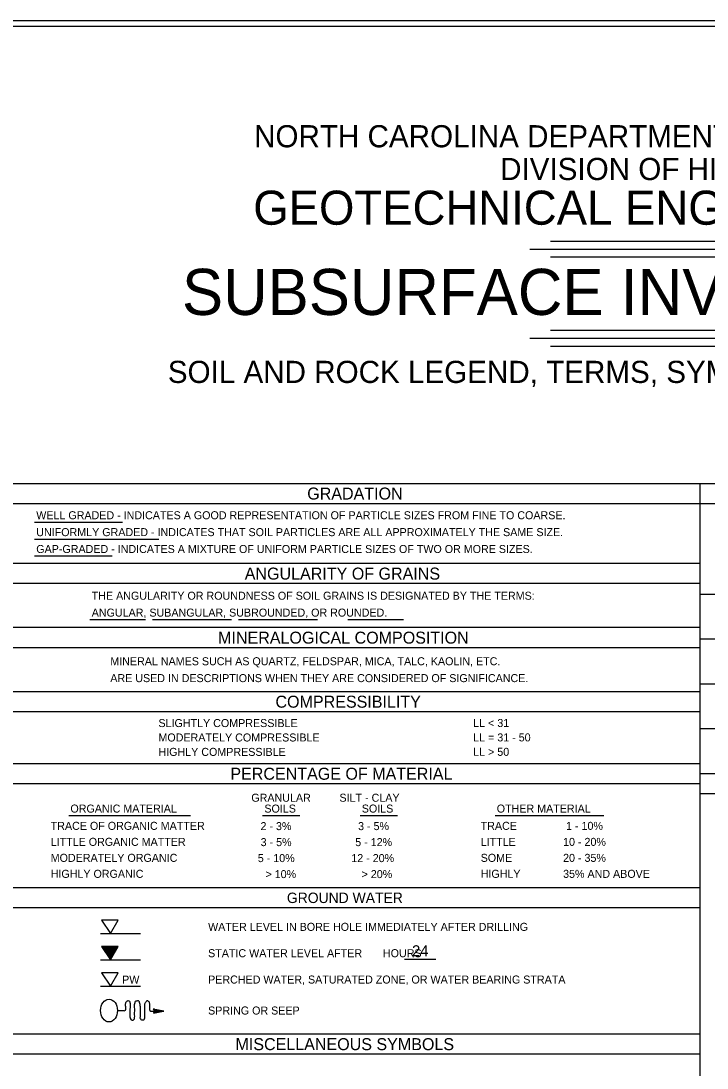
# Model space of a CAD drawing. Extents: x 265553 to 275568, y 168312 to 173522.
# Drawn here: x 267302 to 267674, y 170735 to 171303 of the extents above; entities that cross this region are included whole.
import ezdxf

# ---------------------------------------------------------------- set-up
doc = ezdxf.new("R2010")
doc.units = 0
doc.layers.add('Geotech Sheets and Borders Cell', color=7, linetype='Continuous')
doc.layers.add('Sheet Plot Border Inside CELL', color=7, linetype='Continuous')

msp = doc.modelspace()

# ---------------------------------------------------------------- linework, layer by layer
at = {"layer": 'Geotech Sheets and Borders Cell'}
for p, q in [((267589.55, 171183.48), (267751.29, 171183.48)), ((267578.19, 171179.17), (267762.64, 171179.17)), ((267589.55, 171174.86), (267751.29, 171174.86)), ((267589.55, 171135.21), (267751.29, 171135.21)), ((267578.19, 171130.9), (267762.64, 171130.9)), ((267589.55, 171126.58), (267751.29, 171126.58)), ((266920.42, 171052.08), (268420.42, 171052.08)), ((267670.42, 171052.08), (267670.42, 170249.94)), ((266920.42, 171041.24), (268420.42, 171041.24)), ((267309.79, 171031.16), (267357.41, 171031.16)), ((267309.79, 171022.01), (267377.15, 171022.01)), ((267309.79, 171012.87), (267351.81, 171012.87)), ((267670.42, 171008.7), (267297.82, 171008.7)), ((267670.42, 170997.86), (267297.82, 170997.86)), ((268066.96, 170992), (267670.42, 170992)), ((267339.85, 170978.4), (267369.98, 170978.4)), ((267373.74, 170978.4), (267416.57, 170978.4)), ((267420.33, 170978.4), (267463.16, 170978.4)), ((267479.63, 170978.4), (267509.76, 170978.4)), ((267670.42, 170974), (267297.82, 170974)), ((268066.96, 170967.71), (267670.42, 170967.71)), ((267670.42, 170963.15), (267297.82, 170963.15)), ((267670.42, 170939.29), (267297.82, 170939.29)), ((268066.96, 170943.42), (267670.42, 170943.42)), ((267670.42, 170928.45), (267297.82, 170928.45)), ((268066.96, 170919.12), (267670.42, 170919.12)), ((267670.42, 170900.25), (267297.82, 170900.25)), ((268066.96, 170894.83), (267670.42, 170894.83)), ((267670.42, 170889.41), (267297.82, 170889.41)), ((268066.96, 170883.98), (267670.42, 170883.98)), ((267328.31, 170872.2), (267394.3, 170872.2)), ((267433.44, 170872.2), (267453.66, 170872.2)), ((267486.25, 170872.21), (267506.47, 170872.21)), ((267559.4, 170872.2), (267618.43, 170872.2)), ((267670.42, 170833.01), (267297.82, 170833.01)), ((267670.42, 170822.17), (267297.82, 170822.17)), ((267345.58, 170808.2), (267367.27, 170808.2)), ((267345.58, 170793.93), (267367.27, 170793.93)), ((267510.28, 170794.3), (267527.32, 170794.3)), ((267345.58, 170779.65), (267367.27, 170779.65)), ((267379.87, 170766.26), (267374.14, 170767.34)), ((267374.14, 170767.34), (267374.75, 170766.3)), ((267374.75, 170766.3), (267374.23, 170765.17)), ((267374.23, 170765.17), (267379.73, 170766.21)), ((267374.62, 170766.08), (267377.13, 170766.56)), ((267374.62, 170766.08), (267377.13, 170766.56)), ((267374.62, 170766.04), (267377.13, 170766.52)), ((267374.62, 170766), (267377.13, 170766.47)), ((267374.62, 170765.95), (267377.13, 170766.43)), ((267374.62, 170765.91), (267377.13, 170766.39)), ((267374.62, 170765.91), (267377.13, 170766.39)), ((267374.66, 170765.87), (267377.18, 170766.34)), ((267374.66, 170765.82), (267377.18, 170766.3)), ((267374.66, 170765.78), (267377.18, 170766.26)), ((267374.66, 170765.74), (267377.18, 170766.21)), ((267374.66, 170765.69), (267377.18, 170766.17)), ((267374.66, 170765.65), (267377.18, 170766.13)), ((267374.66, 170765.65), (267377.18, 170766.13)), ((267374.7, 170766.47), (267377.26, 170766.04)), ((267374.7, 170766.47), (267377.26, 170766.04)), ((267374.7, 170766.43), (267377.26, 170766)), ((267374.7, 170765.61), (267377.22, 170766.08)), ((267374.7, 170765.56), (267377.22, 170766.04)), ((267374.7, 170765.52), (267377.22, 170766)), ((267374.7, 170765.48), (267377.22, 170765.95)), ((267374.7, 170765.48), (267377.22, 170765.95)), ((267374.7, 170765.43), (267377.22, 170765.91)), ((267374.75, 170766.78), (267377.31, 170766.34)), ((267374.75, 170766.73), (267377.31, 170766.3)), ((267374.75, 170766.69), (267377.31, 170766.26)), ((267374.75, 170766.65), (267377.31, 170766.21)), ((267374.75, 170766.6), (267377.31, 170766.17)), ((267374.75, 170766.56), (267377.31, 170766.13)), ((267374.75, 170765.39), (267377.26, 170765.87)), ((267374.79, 170766.99), (267377.35, 170766.56)), ((267374.79, 170766.91), (267377.35, 170766.47)), ((267374.79, 170766.86), (267377.35, 170766.43)), ((267374.79, 170766.82), (267377.35, 170766.39)), ((267374.83, 170767.04), (267377.39, 170766.6)), ((267374.88, 170767.12), (267379.56, 170766.26)), ((267670.42, 170753.71), (266920.42, 170753.71)), ((267670.42, 170742.87), (266920.42, 170742.87))]:
    msp.add_line(p, q, dxfattribs=at)
msp.add_lwpolyline([(266920.42, 171299.94), (268420.42, 171299.94), (268420.42, 170249.94), (266920.42, 170249.94)], close=True, dxfattribs=at)
for points in [[(267350.92, 170808.2), (267355.16, 170815.54), (267346.05, 170815.54), (267350.92, 170808.2)], [(267350.92, 170793.93), (267355.16, 170801.25), (267346.05, 170801.25), (267350.92, 170793.93)], [(267346.49, 170800.99), (267354.86, 170800.99), (267350.91, 170794.31), (267346.49, 170800.99)], [(267346.96, 170800.73), (267354.47, 170800.73), (267350.91, 170794.7), (267347.05, 170800.51), (267354.21, 170800.51), (267350.91, 170795.09), (267347.4, 170800.3), (267353.82, 170800.3), (267350.91, 170795.57), (267347.87, 170800.04), (267353.38, 170800.04), (267350.87, 170796.04), (267348.27, 170799.78), (267352.95, 170799.73), (267350.82, 170796.48), (267348.7, 170799.52), (267352.6, 170799.52), (267350.82, 170796.87), (267349.13, 170799.3), (267352.21, 170799.3), (267350.82, 170797.35), (267349.57, 170799.12), (267351.87, 170799.12), (267350.87, 170797.74), (267350.04, 170798.91), (267351.43, 170798.91), (267350.82, 170797.95), (267350.43, 170798.69), (267351.13, 170798.73), (267350.82, 170798.39)], [(267350.92, 170779.65), (267355.16, 170786.98), (267346.05, 170786.98), (267350.92, 170779.65)], [(267374.23, 170767.3), (267374.83, 170766.26), (267374.83, 170767.17), (267374.27, 170767.3), (267374.79, 170766.43), (267374.79, 170767.12), (267374.36, 170767.21), (267374.75, 170766.56), (267374.75, 170767.08), (267374.44, 170767.12), (267374.7, 170766.78), (267374.7, 170766.69), (267374.7, 170766.99), (267374.53, 170767.04), (267374.7, 170767.04), (267374.62, 170766.91), (267374.88, 170766.21), (267374.79, 170766.21), (267374.75, 170766.17), (267374.31, 170765.21), (267374.75, 170765.3), (267374.88, 170766.21), (267374.79, 170766.13), (267374.4, 170765.26), (267374.7, 170765.34), (267374.79, 170766.08), (267374.49, 170765.3), (267374.66, 170765.39), (267374.7, 170765.82), (267374.57, 170765.34), (267374.83, 170765.34), (267379.65, 170766.26)], [(267377.39, 170766.56), (267379.39, 170766.26), (267377.31, 170765.87), (267377.39, 170766.52), (267379.13, 170766.26), (267377.35, 170765.95), (267377.44, 170766.43), (267378.87, 170766.21), (267378.65, 170766.3), (267377.39, 170766.47), (267377.39, 170766), (267378.74, 170766.21), (267377.44, 170766.39), (267377.39, 170766.08), (267378.52, 170766.21), (267377.44, 170766.34), (267377.48, 170766.13), (267378.3, 170766.26), (267377.44, 170766.3), (267377.44, 170766.13), (267378, 170766.3), (267377.48, 170766.21), (267377.44, 170766.04), (267378.04, 170766.13), (267377.48, 170766.6), (267378.3, 170766.43), (267377.39, 170766.6), (267374.83, 170766.3), (267375.09, 170766.21), (267375.18, 170766.26), (267375.18, 170766.3), (267375.4, 170766.3), (267375.4, 170766.34), (267374.96, 170766.95), (267375.79, 170766.78), (267375.74, 170766.91), (267374.88, 170767.08)], [(267374.88, 170766.34), (267375.27, 170766.26), (267374.83, 170766.17), (267375.87, 170766.39), (267374.88, 170766.47), (267375.74, 170766.3), (267375.53, 170766.47), (267374.83, 170766.99), (267376.79, 170766.6), (267377.35, 170766.52), (267377.31, 170765.82), (267377.22, 170766.17)]]:
    msp.add_lwpolyline(points, dxfattribs=at)
msp.add_ellipse((267350.17, 170766.52), major_axis=(0, -6.18), ratio=0.743839, dxfattribs=at)
msp.add_spline([(267354.79, 170766.52), (267358.09, 170766.47), (267358.78, 170766.47), (267359.22, 170768.56), (267359.22, 170770.51), (267359.43, 170771.11), (267359.74, 170771.64), (267360.95, 170771.85), (267361.6, 170770.38), (267361.47, 170766.26), (267361.47, 170763.78), (267361.6, 170762.53), (267362.21, 170761.53), (267363.12, 170761.31), (267363.47, 170761.4), (267364.07, 170762.74), (267364.07, 170764.17), (267364.07, 170768.42), (267364.07, 170769.77), (267364.29, 170770.81), (267364.6, 170771.64), (267365.12, 170771.72), (267365.72, 170771.94), (267366.24, 170771.72), (267366.55, 170771.11), (267366.98, 170768.73), (267366.98, 170764.52), (267366.98, 170763.35), (267367.15, 170762), (267367.81, 170761.53), (267368.63, 170761.4), (267369.24, 170761.7), (267369.54, 170762.53), (267369.54, 170763.78), (267369.54, 170768.64), (267369.54, 170769.55), (267369.84, 170770.59), (267370.15, 170771.11), (267370.49, 170771.64), (267370.8, 170771.94), (267371.19, 170771.85), (267371.71, 170771.42), (267372.01, 170770.72), (267372.14, 170769.9), (267372.14, 170768.03), (267372.14, 170766.99), (267372.75, 170766.17), (267374.1, 170766.26), (267376.57, 170766.26), (267379.87, 170766.26)], degree=3, dxfattribs=at)
at = {"layer": 'Sheet Plot Border Inside CELL'}
msp.add_lwpolyline([(266765.25, 170247.11), (268432.92, 170247.11), (268432.92, 171302.77), (266765.25, 171302.77)], close=True, dxfattribs=at)

# ---------------------------------------------------------------- texts
at = {"layer": 'Geotech Sheets and Borders Cell'}
for s, height, p in [('NORTH CAROLINA DEPARTMENT OF TRANSPORTATION', 12, (267428.8, 171234.3)), ('DIVISION OF HIGHWAYS', 12, (267562.16, 171216.55)), ('GEOTECHNICAL ENGINEERING UNIT', 18.4505, (267428.34, 171192.35)), ('SUBSURFACE INVESTIGATION', 25, (267389.72, 171143.44)), ('SOIL AND ROCK LEGEND, TERMS, SYMBOLS, AND ABBREVIATIONS', 12, (267382.04, 171106.59)), ('GRADATION', 6.507, (267457.61, 171043.41)), ('WELL GRADED - INDICATES A GOOD REPRESENTATION OF PARTICLE SIZES FROM FINE TO COARSE.', 4.3381, (267310.73, 171032.74)), ('UNIFORMLY GRADED - INDICATES THAT SOIL PARTICLES ARE ALL APPROXIMATELY THE SAME SIZE.', 4.3381, (267310.73, 171023.59)), ('GAP-GRADED - INDICATES A MIXTURE OF UNIFORM PARTICLE SIZES OF TWO OR MORE SIZES.', 4.3381, (267310.73, 171014.45)), ('ANGULARITY OF GRAINS', 6.507, (267423.74, 171000.03)), ('THE ANGULARITY OR ROUNDNESS OF SOIL GRAINS IS DESIGNATED BY THE TERMS:', 4.3381, (267340.79, 170989.13)), ('ANGULAR, SUBANGULAR, SUBROUNDED, OR ROUNDED.', 4.3381, (267340.79, 170979.98)), ('MINERALOGICAL COMPOSITION', 6.507, (267409.29, 170965.32)), ('MINERAL NAMES SUCH AS QUARTZ, FELDSPAR, MICA, TALC, KAOLIN, ETC.', 4.3381, (267350.87, 170953.62)), ('ARE USED IN DESCRIPTIONS WHEN THEY ARE CONSIDERED OF SIGNIFICANCE.', 4.3381, (267350.87, 170944.48)), ('COMPRESSIBILITY', 6.507, (267440.39, 170930.62)), ('SLIGHTLY COMPRESSIBLE', 4.3381, (267376.97, 170920.12)), ('LL < 31', 4.338, (267547.58, 170920.16)), ('MODERATELY COMPRESSIBLE', 4.3381, (267376.97, 170912.31)), ('LL = 31 - 50', 4.3381, (267547.58, 170912.35)), ('HIGHLY COMPRESSIBLE', 4.3381, (267376.97, 170904.5)), ('LL > 50', 4.338, (267547.58, 170904.54)), ('PERCENTAGE OF MATERIAL', 6.507, (267415.95, 170891.58)), ('GRANULAR', 4.338, (267427.31, 170879.66)), ('SILT - CLAY', 4.3381, (267475.09, 170879.66)), ('ORGANIC MATERIAL', 4.3381, (267329.25, 170873.78)), ('SOILS', 4.338, (267434.38, 170873.78)), ('SOILS', 4.338, (267487.19, 170873.79)), ('OTHER MATERIAL', 4.3381, (267560.34, 170873.78)), ('TRACE OF ORGANIC MATTER', 4.3381, (267318.56, 170864.43)), ('2 - 3%', 4.338, (267432.29, 170864.28)), ('3 - 5%', 4.338, (267485.17, 170864.28)), ('TRACE', 4.338, (267551.62, 170864.43)), (' 1 - 10%', 4.338, (267596.3, 170864.42)), ('LITTLE ORGANIC MATTER', 4.3381, (267318.56, 170855.76)), ('3 - 5%', 4.338, (267432.36, 170855.61)), ('5 - 12%', 4.338, (267483.63, 170855.61)), ('LITTLE', 4.338, (267551.62, 170855.76)), ('10 - 20%', 4.338, (267596.3, 170855.75)), ('MODERATELY ORGANIC', 4.3381, (267318.56, 170847.09)), ('5 - 10%', 4.338, (267430.82, 170846.95)), ('12 - 20%', 4.338, (267481.51, 170846.95)), ('SOME', 4.338, (267551.62, 170847.09)), ('20 - 35%', 4.338, (267596.3, 170847.08)), ('HIGHLY ORGANIC', 4.3381, (267318.56, 170838.43)), ('> 10%', 4.338, (267434.99, 170838.28)), ('> 20%', 4.338, (267487.08, 170838.28)), ('HIGHLY', 4.338, (267551.62, 170838.43)), ('35% AND ABOVE', 4.3381, (267596.3, 170838.42)), ('GROUND WATER', 5.6395, (267446.59, 170824.77)), ('WATER LEVEL IN BORE HOLE IMMEDIATELY AFTER DRILLING', 4.3381, (267403.88, 170809.7)), ('STATIC WATER LEVEL AFTER       HOURS', 4.3381, (267403.88, 170795.42)), ('24', 6, (267514.4, 170795.88)), ('PW', 4.338, (267357.29, 170781.08)), ('PERCHED WATER, SATURATED ZONE, OR WATER BEARING STRATA', 4.3381, (267403.88, 170781.14)), ('SPRING OR SEEP', 4.3381, (267403.88, 170764.35)), ('MISCELLANEOUS SYMBOLS', 6.507, (267418.72, 170745.04))]:
    msp.add_text(s, height=height, dxfattribs=at).set_placement(p)

doc.saveas('drawing.dxf')
